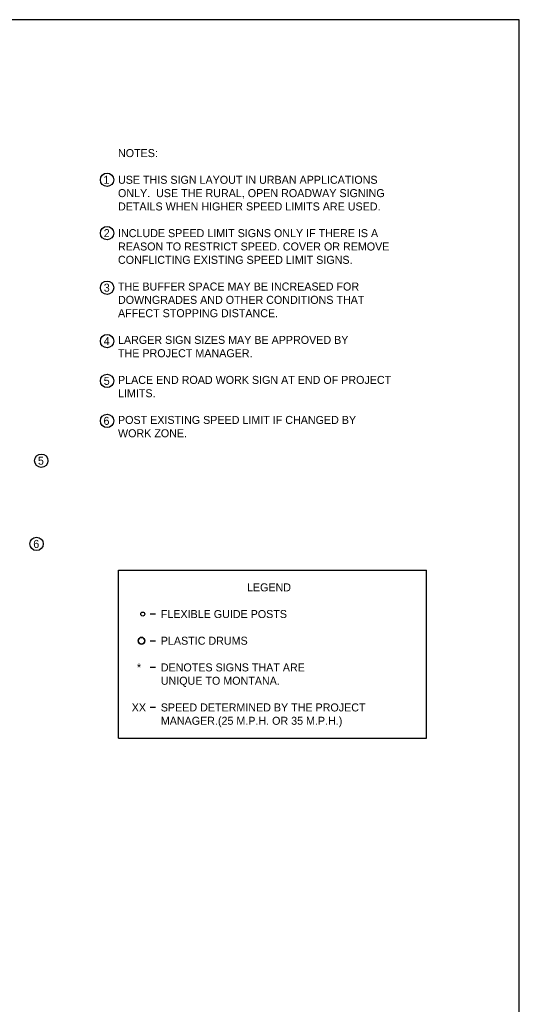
# Model space of a CAD drawing. Extents: x 49991.4 to 50021, y 49987.6 to 50011.4.
# Drawn here: x 50004.87 to 50008.61, y 50003.88 to 50011.26 of the extents above; entities that cross this region are included whole.
import ezdxf

# ---------------------------------------------------------------- set-up
doc = ezdxf.new("R2010")
doc.units = 0
doc.layers.add('Level 1', color=7, linetype='Continuous')
doc.layers.add('Level 2', color=7, linetype='Continuous')

msp = doc.modelspace()

# ---------------------------------------------------------------- linework, layer by layer
at = {"layer": 'Level 1'}
msp.add_lwpolyline([(50008.6146, 50011.2628), (50000.3356, 50011.2628), (50000.3356, 50000.0624), (50008.6146, 50000.0624)], close=True, dxfattribs=at)
for centre, radius in [((50005.7945, 50006.808), 0.015), ((50005.7845, 50006.608), 0.025)]:
    msp.add_circle(centre, radius, dxfattribs=at)
for start, end in [(360, 180), (180, 0)]:
    msp.add_arc((50005.7845, 50006.608), 0.025, start, end, dxfattribs=at)
at = {"layer": 'Level 2'}
for p, q in [((50005.6117, 50007.138), (50007.9184, 50007.138)), ((50005.6117, 50005.8779), (50005.6117, 50007.138)), ((50007.9184, 50005.8779), (50007.9184, 50007.138)), ((50005.8895, 50006.808), (50005.8495, 50006.808)), ((50005.8495, 50006.608), (50005.8895, 50006.608)), ((50005.8895, 50006.408), (50005.8495, 50006.408)), ((50005.8895, 50006.108), (50005.8495, 50006.108)), ((50005.6117, 50005.8779), (50007.9184, 50005.8779))]:
    msp.add_line(p, q, dxfattribs=at)
for centre in [(50005.527, 50010.0629), (50005.527, 50009.6629), (50005.527, 50009.2541), (50005.527, 50008.854), (50005.527, 50008.5559), (50005.527, 50008.2559), (50005.0344, 50007.9573), (50004.9988, 50007.3336)]:
    msp.add_circle(centre, 0.0501, dxfattribs=at)

# ---------------------------------------------------------------- texts
for s, p in [('NOTES:', (50005.609, 50010.2329)), ('1', (50005.4997, 50010.0329)), ('USE THIS SIGN LAYOUT IN URBAN APPLICATIONS', (50005.609, 50010.0329)), ('ONLY.  USE THE RURAL, OPEN ROADWAY SIGNING', (50005.609, 50009.9329)), ('DETAILS WHEN HIGHER SPEED LIMITS ARE USED.', (50005.609, 50009.8329)), ('2', (50005.5021, 50009.6329)), ('INCLUDE SPEED LIMIT SIGNS ONLY IF THERE IS A', (50005.609, 50009.6329)), ('REASON TO RESTRICT SPEED. COVER OR REMOVE', (50005.609, 50009.5329)), ('CONFLICTING EXISTING SPEED LIMIT SIGNS.', (50005.609, 50009.4329)), ('3', (50005.5021, 50009.2241)), ('THE BUFFER SPACE MAY BE INCREASED FOR', (50005.609, 50009.2329)), ('DOWNGRADES AND OTHER CONDITIONS THAT', (50005.609, 50009.1329)), ('AFFECT STOPPING DISTANCE.', (50005.609, 50009.0329)), ('4', (50005.5021, 50008.824)), ('LARGER SIGN SIZES MAY BE APPROVED BY', (50005.609, 50008.8329)), ('THE PROJECT MANAGER.', (50005.609, 50008.7329)), ('5', (50005.5021, 50008.5259)), ('PLACE END ROAD WORK SIGN AT END OF PROJECT', (50005.609, 50008.5329)), ('LIMITS.', (50005.609, 50008.4329)), ('6', (50005.5004, 50008.2259)), ('POST EXISTING SPEED LIMIT IF CHANGED BY', (50005.609, 50008.2329)), ('WORK ZONE.', (50005.609, 50008.1329)), ('5', (50005.0095, 50007.9273)), ('6', (50004.9743, 50007.3036)), ('LEGEND', (50006.5749, 50006.9779)), ('FLEXIBLE GUIDE POSTS', (50005.9295, 50006.778)), ('PLASTIC DRUMS', (50005.9295, 50006.578)), ('*', (50005.7509, 50006.378)), ('DENOTES SIGNS THAT ARE', (50005.9295, 50006.378)), ('UNIQUE TO MONTANA.', (50005.9295, 50006.278)), ('XX', (50005.7117, 50006.078)), ('SPEED DETERMINED BY THE PROJECT', (50005.9295, 50006.078)), ('MANAGER.(25 M.P.H. OR 35 M.P.H.)', (50005.9295, 50005.978))]:
    msp.add_text(s, height=0.06, dxfattribs=at).set_placement(p)

doc.saveas('drawing.dxf')
